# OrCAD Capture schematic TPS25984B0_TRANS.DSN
size C; title: TPS25984B0 Transient spice model; rev: 1.0
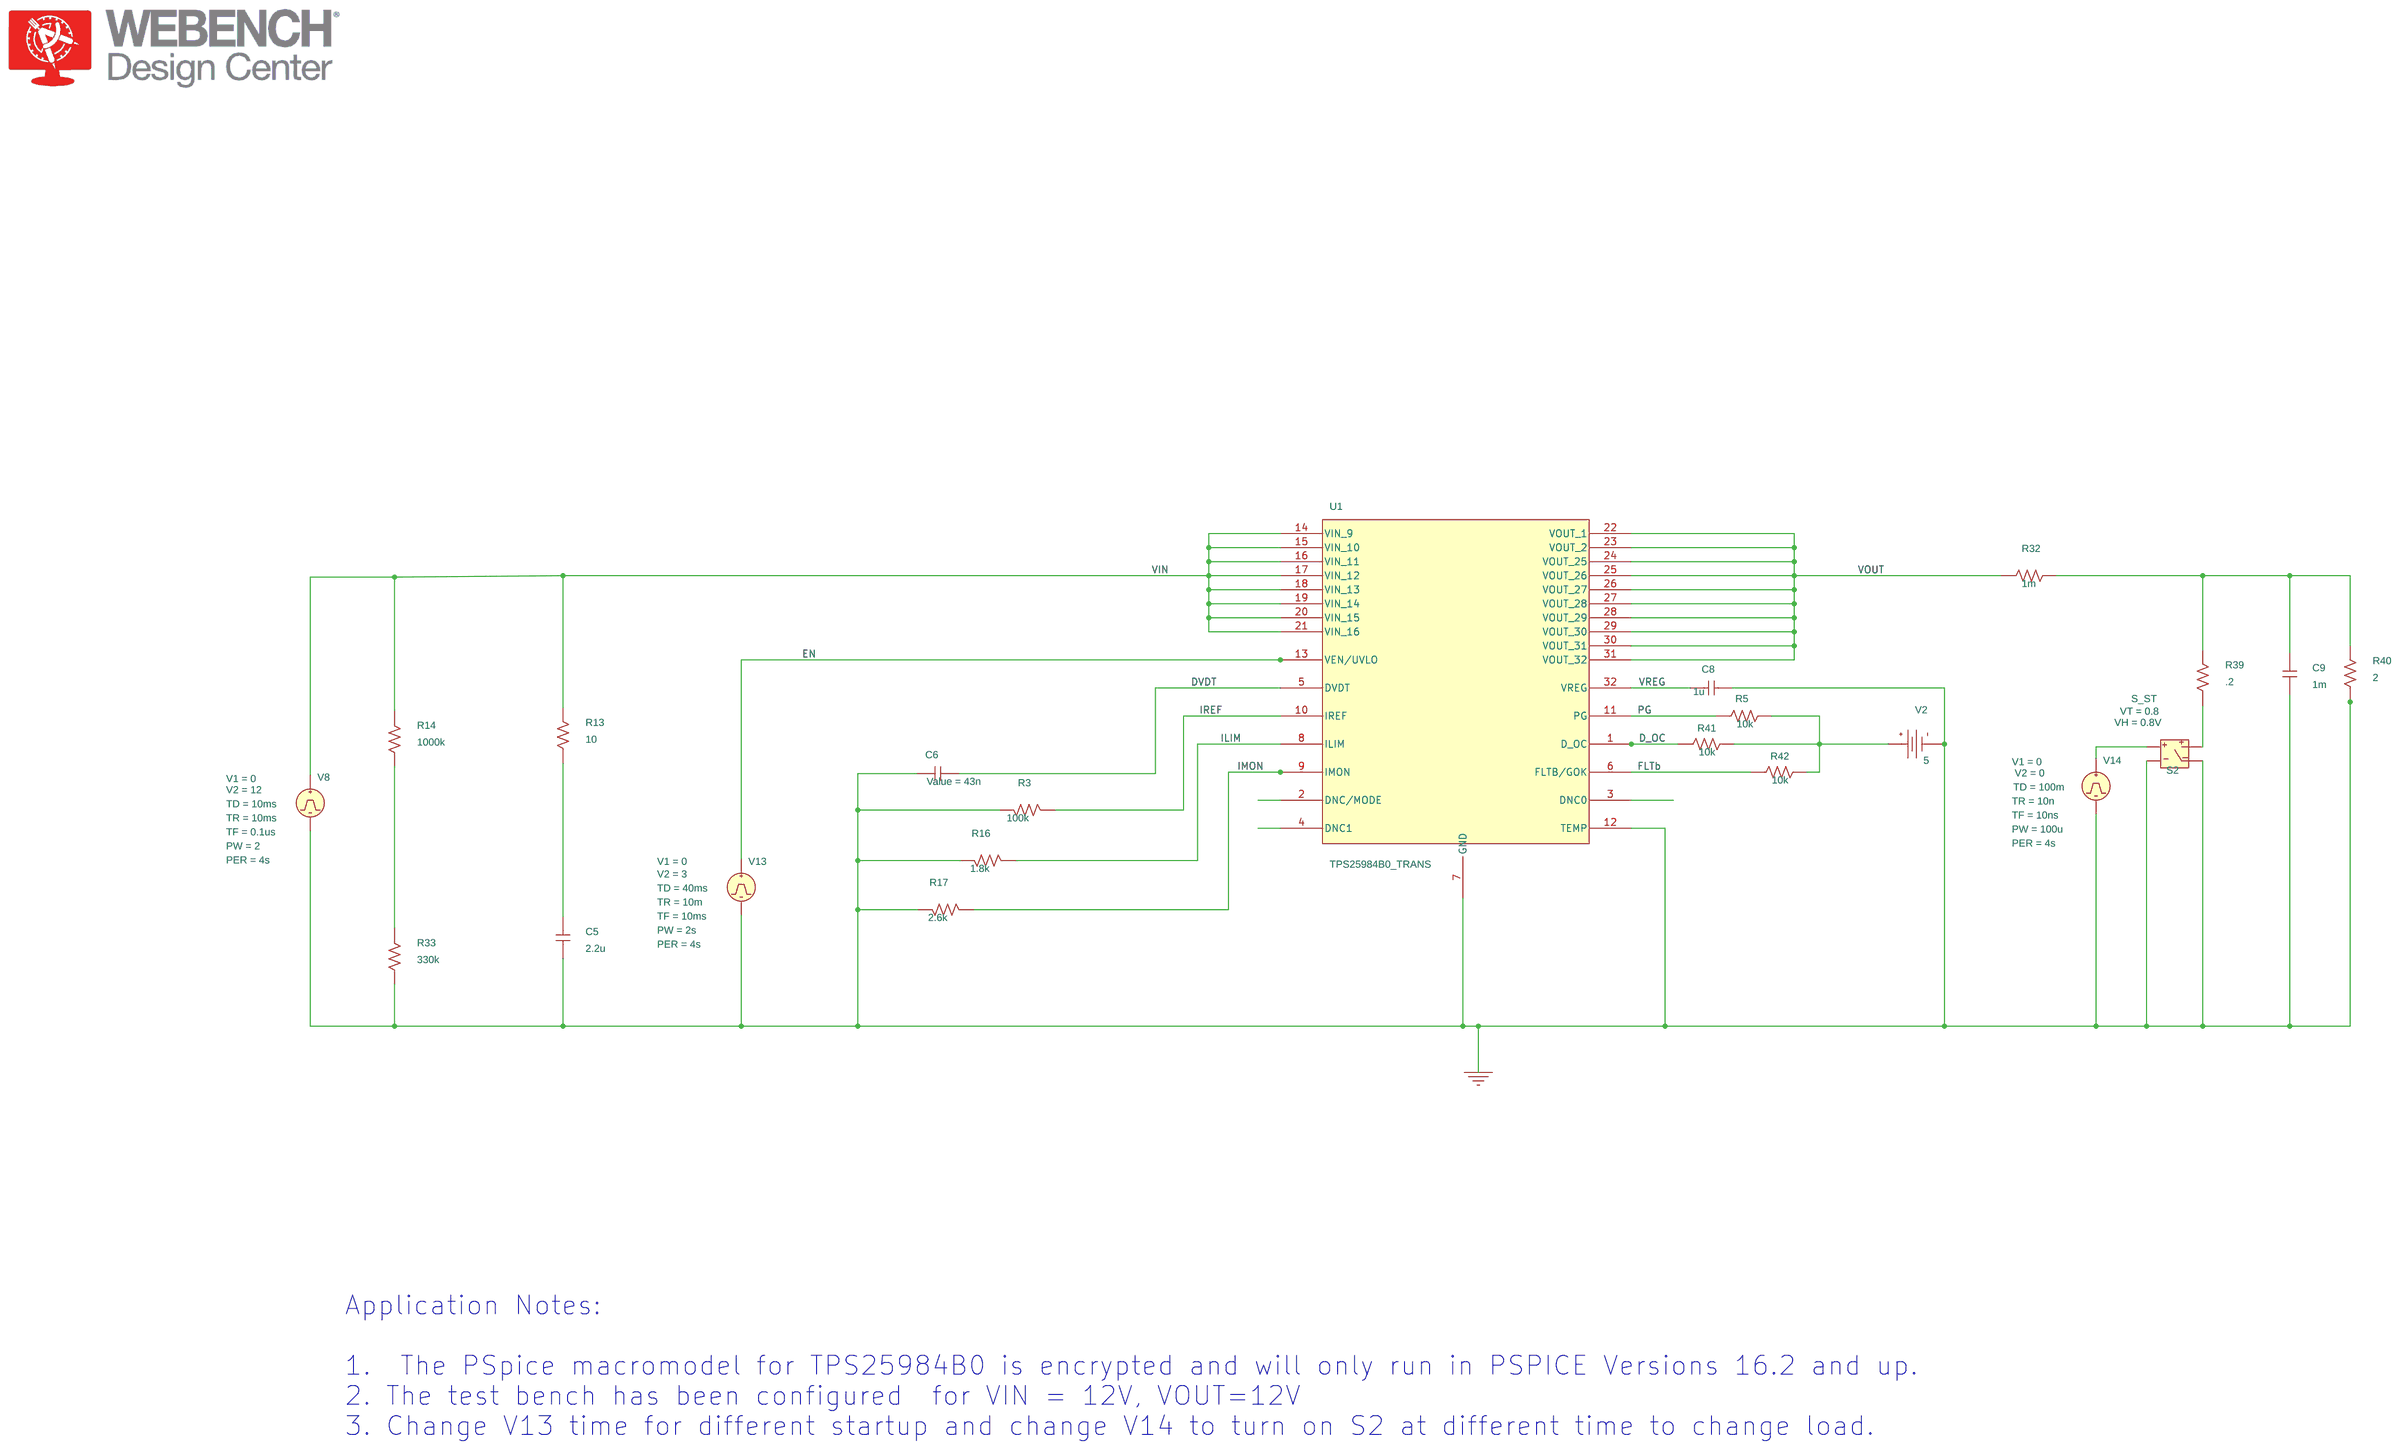
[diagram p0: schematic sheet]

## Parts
C5  2.2u  [RAD/CK05]
C6  43n  [cap196]
C8  1u  [cap196]
C9  1m  [cap196]
R3  100k  [AXRC05]
R5  10k  [AXRC05]
R13  10  [AX/RC05]
R14  1000k  [AX/RC05]
R16  1.8k  [AXRC05]
R17  2.6k  [AXRC05]
R32  1m  [AX/RC05]
R33  330k  [AX/RC05]
R39  .2  [AX/RC05]
R40  2  [AX/RC05]
R41  10k  [AXRC05]
R42  10k  [AXRC05]
S2  S_ST
U1  TPS25984B0_TRANS
V2  VDC
V8  VPULSE
V13  VPULSE
V14  VPULSE

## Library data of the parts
C5 C6 C8 C9 = C
R3 R5 R13 R14 R16 R17 R32 R33 R39-R42 = R
S2 = S_ST: RON: 1u; VH: 0.8V; VT: 0.8
U1 = TPS25984B0_TRANS
V2 = VDC: DC: 5
V8 = VPULSE: PER: 4s; PW: 2; TD: 10ms; TF: 0.1us; TR: 10ms; V1: 0; V2: 12
V13 = VPULSE: PER: 4s; PW: 2s; TD: 40ms; TF: 10ms; TR: 10m; V1: 0; V2: 3
V14 = VPULSE: PER: 4s; PW: 100u; TD: 100m; TF: 10ns; TR: 10n; V1: 0; V2: 0

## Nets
VIN: R13.2 R14.1 U1.14(VIN_9) U1.15(VIN_10) U1.16(VIN_11) U1.17(VIN_12) U1.18(VIN_13) U1.19(VIN_14) U1.20(VIN_15) U1.21(VIN_16) V8.1(+)
0: C5.1 C6.2 C8.1 C9.1 R3.2 R16.2 R17.2 R33.2 R40.1 S2.1(2) S2.3(4) U1.7(GND) U1.12(TEMP) V2.1(-) V8.2(-) V13.2(-) V14.2(-)
D_OC: R41.1 U1.1(D_OC)
DVDT: C6.1 U1.5(DVDT)
EN: U1.13(VEN/UVLO) V13.1(+)
FLTb: R42.1 U1.6(FLTB/GOK)
ILIM: R16.1 U1.8(ILIM)
IMON: R17.1 U1.9(IMON)
IREF: R3.1 U1.10(IREF)
PG: R5.1 U1.11(PG)
VOUT: R32.1 U1.22(VOUT_1) U1.23(VOUT_2) U1.24(VOUT_25) U1.25(VOUT_26) U1.26(VOUT_27) U1.27(VOUT_28) U1.28(VOUT_29) U1.29(VOUT_30) U1.30(VOUT_31) U1.31(VOUT_32)
VREG: C8.2 U1.32(VREG)
N351412: C5.2 R13.1
N351472: R14.2 R33.1
N354534: C9.2 R32.2 R39.2 R40.2
N354658: S2.0(1) V14.1(+)
N355435: R5.2 R41.2 R42.2 V2.0(+)
N369917: R39.1 S2.2(3)

Not connected (* = marked no-connect by the designer): U1 2(DNC/MODE) 3(DNC0) 4(DNC1)

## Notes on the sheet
- Application Notes:
  1.  The PSpice macromodel for TPS25984B0 is encrypted and will only run in PSPICE Versions 16.2 and up.
  2. The test bench has been configured  for VIN = 12V, VOUT=12V
  3. Change V13 time for different startup and change V14 to turn on S2 at different time to change load.
